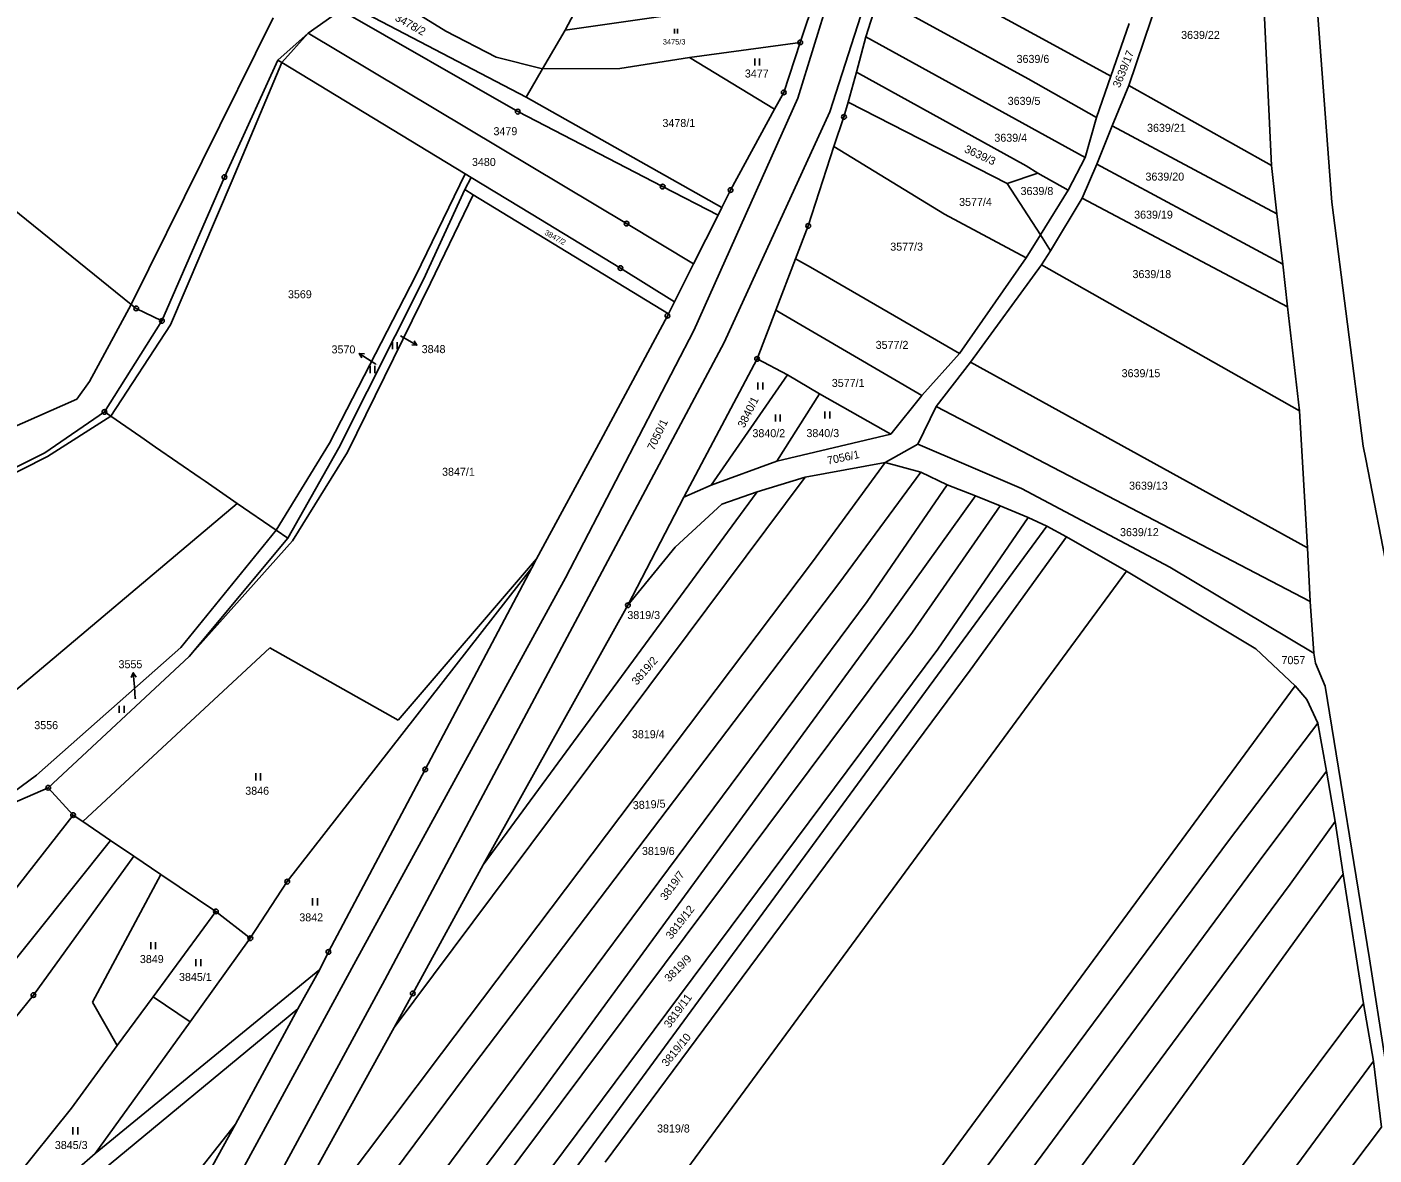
# Model space of a CAD drawing. Extents: x -593183 to -588034, y -1130415 to -1124994.
# Drawn here: x -592616.5 to -592330.3, y -1129503.7 to -1129264.2 of the extents above; entities that cross this region are included whole.
import ezdxf

# ---------------------------------------------------------------- set-up
doc = ezdxf.new("R2010")
doc.units = 0
for name, color, linetype in [('Vrstva 1', 7, 'Continuous'), ('Vrstva 16', 7, 'Continuous'), ('Vrstva 18', 7, 'Continuous'), ('Vrstva 24', 7, 'Continuous'), ('Vrstva 25', 7, 'Continuous'), ('Vrstva 4', 7, 'Continuous')]:
    doc.layers.add(name, color=color, linetype=linetype)

msp = doc.modelspace()

# ---------------------------------------------------------------- linework, layer by layer
at = {"layer": 'Vrstva 1'}
for p, q in [((-592502.17, -1129264.93), (-592488.76, -1129239.64)), ((-592372.43, -1129247.28), (-592382.39, -1129276.63)), ((-592433.18, -1129249.11), (-592399.16, -1129267.58)), ((-592547.28, -1129252.87), (-592527.55, -1129265.11)), ((-592448.45, -1129256.14), (-592452.23, -1129267.51)), ((-592435.59, -1129257.8), (-592438.25, -1129266.31)), ((-592435.59, -1129257.8), (-592403.79, -1129275.27)), ((-592353.74, -1129259.3), (-592352.1, -1129293.67)), ((-592342.42, -1129259), (-592339.24, -1129301.4)), ((-592564.21, -1129262.32), (-592594.34, -1129323.16)), ((-592549.85, -1129260.67), (-592556.77, -1129265.52)), ((-592549.85, -1129260.67), (-592512.23, -1129282.21)), ((-592502.17, -1129264.93), (-592475.9, -1129261.13)), ((-592527.55, -1129265.11), (-592516.81, -1129270.62)), ((-592506.96, -1129273.15), (-592502.17, -1129264.93)), ((-592386.24, -1129274.66), (-592382.35, -1129263.47)), ((-592556.77, -1129265.52), (-592563.19, -1129271.28)), ((-592556.77, -1129265.52), (-592489.11, -1129305.98)), ((-592475.78, -1129270.69), (-592452.23, -1129267.51)), ((-592455.72, -1129278.13), (-592452.23, -1129267.51)), ((-592438.25, -1129266.31), (-592440.26, -1129273.86)), ((-592438.25, -1129266.31), (-592391.7, -1129291.93)), ((-592399.16, -1129267.58), (-592386.24, -1129274.66)), ((-592516.81, -1129270.62), (-592506.96, -1129273.15)), ((-592490.56, -1129273.03), (-592475.78, -1129270.69)), ((-592475.78, -1129270.69), (-592457.69, -1129281.69)), ((-592563.19, -1129271.28), (-592574.56, -1129296.11)), ((-592563.19, -1129271.28), (-592562.34, -1129271.8)), ((-592562.34, -1129271.8), (-592523.43, -1129295.39)), ((-592506.96, -1129273.15), (-592510.46, -1129279.15)), ((-592506.96, -1129273.15), (-592490.56, -1129273.03)), ((-592440.26, -1129273.86), (-592442.04, -1129280.18)), ((-592440.26, -1129273.86), (-592404.18, -1129293.74)), ((-592403.79, -1129275.27), (-592389.3, -1129283.48)), ((-592389.3, -1129283.48), (-592386.24, -1129274.66)), ((-592382.39, -1129276.63), (-592385.96, -1129285.21)), ((-592382.39, -1129276.63), (-592352.1, -1129293.67)), ((-592510.46, -1129279.15), (-592468.85, -1129302.54)), ((-592457.69, -1129281.69), (-592455.72, -1129278.13)), ((-592512.23, -1129282.21), (-592481.45, -1129298.11)), ((-592457.69, -1129281.69), (-592467.01, -1129298.87)), ((-592442.04, -1129280.18), (-592442.92, -1129283.33)), ((-592442.04, -1129280.18), (-592408.23, -1129297.46)), ((-592442.92, -1129283.33), (-592445.06, -1129289.63)), ((-592391.7, -1129291.93), (-592389.3, -1129283.48)), ((-592385.96, -1129285.21), (-592389.19, -1129293.36)), ((-592385.96, -1129285.21), (-592350.93, -1129303.88)), ((-592450.52, -1129306.46), (-592445.06, -1129289.63)), ((-592445.06, -1129289.63), (-592421.59, -1129303.96)), ((-592404.18, -1129293.74), (-592401.75, -1129295.29)), ((-592395.3, -1129298.88), (-592391.7, -1129291.93)), ((-592389.19, -1129293.36), (-592392.33, -1129300.61)), ((-592389.19, -1129293.36), (-592349.69, -1129314.61)), ((-592352.1, -1129293.67), (-592350.93, -1129303.88)), ((-592629.53, -1129294.78), (-592594.34, -1129323.16)), ((-592574.56, -1129296.11), (-592587.83, -1129326.65)), ((-592533.9, -1129317.03), (-592523.43, -1129295.39)), ((-592522.15, -1129296.17), (-592523.48, -1129298.75)), ((-592523.43, -1129295.39), (-592522.15, -1129296.17)), ((-592522.15, -1129296.17), (-592509.4, -1129303.91)), ((-592401.75, -1129295.29), (-592408.23, -1129297.46)), ((-592401.75, -1129295.29), (-592395.3, -1129298.88)), ((-592523.48, -1129298.75), (-592532.29, -1129317.84)), ((-592523.48, -1129298.75), (-592521.71, -1129299.9)), ((-592481.45, -1129298.11), (-592469.69, -1129304.19)), ((-592467.01, -1129298.87), (-592468.85, -1129302.54)), ((-592408.23, -1129297.46), (-592401.17, -1129308.35)), ((-592395.3, -1129298.88), (-592401.17, -1129308.35)), ((-592521.71, -1129299.9), (-592530.77, -1129318.6)), ((-592521.71, -1129299.9), (-592480.21, -1129325.16)), ((-592468.85, -1129302.54), (-592469.69, -1129304.19)), ((-592392.33, -1129300.61), (-592399.01, -1129311.78)), ((-592392.33, -1129300.61), (-592348.66, -1129323.62)), ((-592339.24, -1129301.4), (-592332.6, -1129353.21)), ((-592509.4, -1129303.91), (-592490.42, -1129315.43)), ((-592474.88, -1129314.49), (-592469.69, -1129304.19)), ((-592421.59, -1129303.96), (-592404.19, -1129313.23)), ((-592350.93, -1129303.88), (-592349.69, -1129314.61)), ((-592489.11, -1129305.98), (-592474.88, -1129314.49)), ((-592453.21, -1129313.45), (-592450.52, -1129306.46)), ((-592401.17, -1129308.35), (-592404.19, -1129313.23)), ((-592401.17, -1129308.35), (-592399.01, -1129311.78)), ((-592457.4, -1129324.37), (-592453.21, -1129313.45)), ((-592453.21, -1129313.45), (-592450.07, -1129315.26)), ((-592404.19, -1129313.23), (-592418.36, -1129333.55)), ((-592399.01, -1129311.78), (-592400.95, -1129314.72)), ((-592490.42, -1129315.43), (-592478.93, -1129322.6)), ((-592478.93, -1129322.6), (-592474.88, -1129314.49)), ((-592450.07, -1129315.26), (-592418.36, -1129333.55)), ((-592416.06, -1129335.42), (-592400.95, -1129314.72)), ((-592400.95, -1129314.72), (-592346.12, -1129345.7)), ((-592349.69, -1129314.61), (-592348.66, -1129323.62)), ((-592552.25, -1129352.59), (-592533.9, -1129317.03)), ((-592550.28, -1129353.58), (-592532.29, -1129317.84)), ((-592530.77, -1129318.6), (-592548.4, -1129354.52)), ((-592480.21, -1129325.16), (-592478.93, -1129322.6)), ((-592603.26, -1129339.52), (-592594.34, -1129323.16)), ((-592594.34, -1129323.16), (-592593.3, -1129324)), ((-592593.3, -1129324), (-592587.83, -1129326.65)), ((-592480.21, -1129325.16), (-592480.45, -1129325.55)), ((-592461.37, -1129334.71), (-592457.4, -1129324.37)), ((-592457.4, -1129324.37), (-592456.67, -1129324.8)), ((-592456.67, -1129324.8), (-592426.38, -1129342.5)), ((-592348.66, -1129323.62), (-592346.12, -1129345.7)), ((-592587.83, -1129326.65), (-592600.05, -1129345.96)), ((-592480.45, -1129325.55), (-592494.59, -1129351.94)), ((-592418.36, -1129333.55), (-592426.38, -1129342.5)), ((-592476.93, -1129364.09), (-592461.37, -1129334.71)), ((-592461.37, -1129334.71), (-592454.95, -1129338.11)), ((-592423.37, -1129344.79), (-592416.06, -1129335.42)), ((-592416.06, -1129335.42), (-592344.41, -1129374.8)), ((-592605.95, -1129343.28), (-592603.26, -1129339.52)), ((-592471.12, -1129361.54), (-592454.95, -1129338.11)), ((-592454.95, -1129338.11), (-592448.13, -1129342.09)), ((-592457.18, -1129356.39), (-592448.13, -1129342.09)), ((-592448.13, -1129342.09), (-592432.98, -1129350.71)), ((-592426.38, -1129342.5), (-592432.98, -1129350.71)), ((-592638.13, -1129357.46), (-592605.95, -1129343.28)), ((-592427.26, -1129352.84), (-592423.37, -1129344.79)), ((-592423.37, -1129344.79), (-592343.89, -1129386.22)), ((-592600.05, -1129345.96), (-592612.74, -1129354.62)), ((-592598.73, -1129346.87), (-592612.18, -1129355.44)), ((-592600.05, -1129345.96), (-592598.73, -1129346.87)), ((-592598.73, -1129346.87), (-592592.31, -1129351.28)), ((-592346.12, -1129345.7), (-592344.41, -1129374.8)), ((-592432.98, -1129350.71), (-592457.18, -1129356.39)), ((-592592.31, -1129351.28), (-592589.18, -1129353.43)), ((-592589.18, -1129353.43), (-592579.72, -1129359.95)), ((-592552.25, -1129352.59), (-592563.58, -1129371.04)), ((-592561.07, -1129372.77), (-592550.28, -1129353.58)), ((-592494.59, -1129351.94), (-592508.27, -1129377.17)), ((-592434.18, -1129356.68), (-592427.26, -1129352.84)), ((-592427.26, -1129352.84), (-592405.17, -1129362.25)), ((-592332.6, -1129353.21), (-592332.07, -1129355.97)), ((-592612.74, -1129354.62), (-592625.77, -1129361.15)), ((-592612.18, -1129355.44), (-592625.16, -1129361.95)), ((-592548.4, -1129354.52), (-592560.11, -1129373.31)), ((-592457.18, -1129356.39), (-592471.12, -1129361.54)), ((-592451.18, -1129359.81), (-592434.18, -1129356.68)), ((-592449.63, -1129377.77), (-592434.18, -1129356.68)), ((-592434.18, -1129356.68), (-592426.58, -1129358.74)), ((-592332.07, -1129355.97), (-592327.01, -1129381.91)), ((-592451.18, -1129359.81), (-592538.53, -1129476.7)), ((-592461.37, -1129362.95), (-592451.18, -1129359.81)), ((-592426.58, -1129358.74), (-592444, -1129382.37)), ((-592426.58, -1129358.74), (-592420.99, -1129361.46)), ((-592579.72, -1129359.95), (-592578.65, -1129360.68)), ((-592578.65, -1129360.68), (-592571.82, -1129365.38)), ((-592471.12, -1129361.54), (-592476.93, -1129364.09)), ((-592420.99, -1129361.46), (-592438.02, -1129386.19)), ((-592420.99, -1129361.46), (-592415.01, -1129363.8)), ((-592405.17, -1129362.25), (-592373.69, -1129378.91)), ((-592571.82, -1129365.38), (-592625.68, -1129410.77)), ((-592571.82, -1129365.38), (-592563.58, -1129371.04)), ((-592476.93, -1129364.09), (-592488.83, -1129387)), ((-592468.86, -1129365.56), (-592461.37, -1129362.95)), ((-592461.37, -1129362.95), (-592465.88, -1129369.1)), ((-592415.01, -1129363.8), (-592433.12, -1129389.07)), ((-592415.01, -1129363.8), (-592409.77, -1129365.91)), ((-592478.77, -1129374.68), (-592468.86, -1129365.56)), ((-592409.77, -1129365.91), (-592428.37, -1129392.7)), ((-592403.81, -1129368.39), (-592422.95, -1129396.37)), ((-592409.77, -1129365.91), (-592403.81, -1129368.39)), ((-592403.81, -1129368.39), (-592399.79, -1129370.25)), ((-592563.58, -1129371.04), (-592583.8, -1129395.99)), ((-592563.58, -1129371.04), (-592561.07, -1129372.77)), ((-592465.88, -1129369.1), (-592519.59, -1129442.1)), ((-592399.79, -1129370.25), (-592497.07, -1129502.63)), ((-592399.79, -1129370.25), (-592395.63, -1129372.45)), ((-592582.03, -1129397.89), (-592561.07, -1129372.77)), ((-592560.11, -1129373.31), (-592582.03, -1129397.89)), ((-592395.63, -1129372.45), (-592416.09, -1129400.77)), ((-592395.63, -1129372.45), (-592382.89, -1129379.81)), ((-592488.83, -1129387), (-592478.77, -1129374.68)), ((-592344.41, -1129374.8), (-592343.89, -1129386.22)), ((-592509.21, -1129379.05), (-592561.2, -1129445.7)), ((-592537.66, -1129411.4), (-592508.27, -1129377.17)), ((-592509.21, -1129379.05), (-592531.89, -1129421.87)), ((-592528.41, -1129482.16), (-592449.63, -1129377.77)), ((-592508.27, -1129377.17), (-592509.21, -1129379.05)), ((-592382.89, -1129379.81), (-592404.58, -1129409.23)), ((-592382.89, -1129379.81), (-592355.42, -1129396.25)), ((-592373.69, -1129378.91), (-592343.09, -1129397.21)), ((-592444, -1129382.37), (-592523.23, -1129486.72)), ((-592438.02, -1129386.19), (-592571.09, -1129565.21)), ((-592488.83, -1129387), (-592519.59, -1129442.1)), ((-592343.89, -1129386.22), (-592343.09, -1129397.21)), ((-592433.12, -1129389.07), (-592508.72, -1129492.45)), ((-592428.37, -1129392.7), (-592615.11, -1129642.53)), ((-592583.8, -1129395.99), (-592614.52, -1129423.06)), ((-592604.64, -1129432.96), (-592564.92, -1129396.07)), ((-592537.66, -1129411.4), (-592564.92, -1129396.07)), ((-592422.95, -1129396.37), (-592556.78, -1129575.72)), ((-592355.42, -1129396.25), (-592347.06, -1129404.11)), ((-592612, -1129425.77), (-592582.03, -1129397.89)), ((-592343.09, -1129397.21), (-592342.77, -1129399.3)), ((-592342.77, -1129399.3), (-592340.69, -1129404.16)), ((-592416.09, -1129400.77), (-592493.66, -1129505.27)), ((-592347.06, -1129404.11), (-592422.06, -1129506.07)), ((-592347.06, -1129404.11), (-592344.55, -1129407.03)), ((-592340.69, -1129404.16), (-592331.28, -1129462.11)), ((-592344.55, -1129407.03), (-592342.25, -1129412.06)), ((-592404.58, -1129409.23), (-592534.96, -1129586.45)), ((-592342.25, -1129412.06), (-592361, -1129436.75)), ((-592342.25, -1129412.06), (-592340.38, -1129422.25)), ((-592552.45, -1129460.63), (-592531.89, -1129421.87)), ((-592340.38, -1129422.25), (-592354.68, -1129441.35)), ((-592340.38, -1129422.25), (-592338.57, -1129432.91)), ((-592614.52, -1129423.06), (-592626.89, -1129432.2)), ((-592626.89, -1129432.2), (-592612, -1129425.77)), ((-592612, -1129425.77), (-592606.7, -1129431.58)), ((-592606.7, -1129431.58), (-592635.24, -1129467.95)), ((-592606.7, -1129431.58), (-592604.64, -1129432.96)), ((-592604.64, -1129432.96), (-592598.77, -1129436.95)), ((-592338.57, -1129432.91), (-592348.11, -1129446.26)), ((-592338.57, -1129432.91), (-592336.85, -1129444.12)), ((-592598.77, -1129436.95), (-592728.12, -1129598.57)), ((-592598.77, -1129436.95), (-592593.78, -1129440.28)), ((-592361, -1129436.75), (-592443.04, -1129547.16)), ((-592593.78, -1129440.28), (-592615.14, -1129469.78)), ((-592593.78, -1129440.28), (-592588.04, -1129444.15)), ((-592519.59, -1129442.1), (-592534.54, -1129469.44)), ((-592354.68, -1129441.35), (-592435.72, -1129550.87)), ((-592588.04, -1129444.15), (-592602.57, -1129471.27)), ((-592588.04, -1129444.15), (-592576.37, -1129452.02)), ((-592542.16, -1129727.88), (-592336.85, -1129444.12)), ((-592336.85, -1129444.12), (-592332.56, -1129471.56)), ((-592569.06, -1129457.7), (-592561.2, -1129445.7)), ((-592348.11, -1129446.26), (-592429.15, -1129555.51)), ((-592589.69, -1129470.13), (-592576.37, -1129452.02)), ((-592576.37, -1129452.02), (-592569.06, -1129457.7)), ((-592581.87, -1129475.49), (-592569.06, -1129457.7)), ((-592554.32, -1129464.36), (-592552.45, -1129460.63)), ((-592331.28, -1129462.11), (-592324.59, -1129504.82)), ((-592601.99, -1129503.41), (-592554.32, -1129464.36)), ((-592554.32, -1129464.36), (-592558.93, -1129472.7)), ((-592615.14, -1129469.78), (-592673.78, -1129542.41)), ((-592602.57, -1129471.27), (-592597.32, -1129480.5)), ((-592597.32, -1129480.5), (-592589.69, -1129470.13)), ((-592589.69, -1129470.13), (-592581.87, -1129475.49)), ((-592534.54, -1129469.44), (-592538.53, -1129476.7)), ((-592558.93, -1129472.7), (-592609.92, -1129514.75)), ((-592558.93, -1129472.7), (-592572.22, -1129497.21)), ((-592332.56, -1129471.56), (-592403.4, -1129566.28)), ((-592332.56, -1129471.56), (-592330.41, -1129483.83)), ((-592581.87, -1129475.49), (-592601.99, -1129503.41)), ((-592538.53, -1129476.7), (-592561.73, -1129518.61)), ((-592597.32, -1129480.5), (-592607.08, -1129493.77)), ((-592528.41, -1129482.16), (-592577.74, -1129547.59)), ((-592330.41, -1129483.83), (-592400.03, -1129577.94)), ((-592330.41, -1129483.83), (-592328.74, -1129497.8)), ((-592523.23, -1129486.72), (-592578.35, -1129560.66)), ((-592619.46, -1129509.25), (-592607.08, -1129493.77)), ((-592508.72, -1129492.45), (-592566.4, -1129568.69)), ((-592572.22, -1129497.21), (-592660.77, -1129609.53)), ((-592572.22, -1129497.21), (-592578.59, -1129508.75)), ((-592328.74, -1129497.8), (-592392.56, -1129582.82)), ((-592553.2, -1129578.42), (-592497.07, -1129502.63)), ((-592614.6, -1129514.29), (-592601.99, -1129503.41))]:
    msp.add_line(p, q, dxfattribs=at)
at = {"layer": 'Vrstva 16'}
for p, q in [((-592537.16, -1129329.81), (-592536.27, -1129330.31)), ((-592542.36, -1129335.83), (-592543.4, -1129335.16)), ((-592593.52, -1129406.91), (-592593.7, -1129404.34))]:
    msp.add_line(p, q, dxfattribs=at)
at = {"layer": 'Vrstva 24'}
for centre, radius in [((-592452.23, -1129267.51), 0.5), ((-592452.23, -1129267.51), 0.0327), ((-592455.72, -1129278.13), 0.5), ((-592455.72, -1129278.13), 0.0327), ((-592512.23, -1129282.21), 0.5), ((-592512.23, -1129282.21), 0.0327), ((-592442.92, -1129283.33), 0.5), ((-592442.92, -1129283.33), 0.0327), ((-592574.56, -1129296.11), 0.5), ((-592574.56, -1129296.11), 0.0327), ((-592481.45, -1129298.11), 0.5), ((-592481.45, -1129298.11), 0.0327), ((-592467.01, -1129298.87), 0.5), ((-592467.01, -1129298.87), 0.0327), ((-592489.11, -1129305.98), 0.5), ((-592489.11, -1129305.98), 0.0327), ((-592450.52, -1129306.46), 0.5), ((-592450.52, -1129306.46), 0.0327), ((-592490.42, -1129315.43), 0.5), ((-592490.42, -1129315.43), 0.0327), ((-592593.3, -1129324), 0.5), ((-592593.3, -1129324), 0.0327), ((-592480.45, -1129325.55), 0.5), ((-592587.83, -1129326.65), 0.5), ((-592587.83, -1129326.65), 0.0327), ((-592480.45, -1129325.55), 0.0327), ((-592461.37, -1129334.71), 0.5), ((-592461.37, -1129334.71), 0.0327), ((-592600.05, -1129345.96), 0.5), ((-592600.05, -1129345.96), 0.0327), ((-592488.83, -1129387), 0.5), ((-592488.83, -1129387), 0.0327), ((-592531.89, -1129421.87), 0.5), ((-592531.89, -1129421.87), 0.0327), ((-592612, -1129425.77), 0.5), ((-592612, -1129425.77), 0.0327), ((-592606.7, -1129431.58), 0.5), ((-592606.7, -1129431.58), 0.0327), ((-592561.2, -1129445.7), 0.5), ((-592561.2, -1129445.7), 0.0327), ((-592576.37, -1129452.02), 0.5), ((-592576.37, -1129452.02), 0.0327), ((-592569.06, -1129457.7), 0.5), ((-592569.06, -1129457.7), 0.0327), ((-592552.45, -1129460.63), 0.5), ((-592552.45, -1129460.63), 0.0327), ((-592615.14, -1129469.78), 0.5), ((-592615.14, -1129469.78), 0.0327), ((-592534.54, -1129469.44), 0.5), ((-592534.54, -1129469.44), 0.0327)]:
    msp.add_circle(centre, radius, dxfattribs=at)
at = {"layer": 'Vrstva 25'}
for p, q in [((-592478.95, -1129264.64), (-592478.95, -1129265.64)), ((-592478.26, -1129265.64), (-592478.26, -1129264.64)), ((-592461.89, -1129270.94), (-592461.89, -1129272.44)), ((-592460.86, -1129272.44), (-592460.86, -1129270.94)), ((-592538.85, -1129331.14), (-592538.85, -1129332.64)), ((-592537.83, -1129332.64), (-592537.83, -1129331.14)), ((-592536.27, -1129330.31), (-592533.65, -1129331.78)), ((-592543.4, -1129335.16), (-592545.92, -1129333.54)), ((-592543.61, -1129336.2), (-592543.61, -1129337.7)), ((-592542.59, -1129337.7), (-592542.59, -1129336.2)), ((-592461.2, -1129339.7), (-592461.2, -1129341.2)), ((-592460.18, -1129341.2), (-592460.18, -1129339.7)), ((-592457.49, -1129346.49), (-592457.49, -1129347.99)), ((-592456.47, -1129347.99), (-592456.47, -1129346.49)), ((-592446.97, -1129345.89), (-592446.97, -1129347.39)), ((-592445.95, -1129347.39), (-592445.95, -1129345.89)), ((-592593.7, -1129404.34), (-592593.92, -1129401.35)), ((-592596.9, -1129408.36), (-592596.9, -1129409.86)), ((-592595.88, -1129409.86), (-592595.88, -1129408.36)), ((-592567.9, -1129422.69), (-592567.9, -1129424.19)), ((-592566.88, -1129424.19), (-592566.88, -1129422.69)), ((-592555.84, -1129449.24), (-592555.84, -1129450.74)), ((-592554.82, -1129450.74), (-592554.82, -1129449.24)), ((-592590.22, -1129458.52), (-592590.22, -1129460.02)), ((-592589.2, -1129460.02), (-592589.2, -1129458.52)), ((-592580.62, -1129462.15), (-592580.62, -1129463.65)), ((-592579.59, -1129463.65), (-592579.59, -1129462.15)), ((-592606.74, -1129497.85), (-592606.74, -1129499.35)), ((-592605.72, -1129499.35), (-592605.72, -1129497.85))]:
    msp.add_line(p, q, dxfattribs=at)
for points in [[(-592534.28, -1129330.85), (-592533.65, -1129331.78), (-592534.77, -1129331.72)], [(-592545.35, -1129334.5), (-592545.92, -1129333.54), (-592544.81, -1129333.66)], [(-592594.34, -1129402.38), (-592593.92, -1129401.35), (-592593.34, -1129402.31)]]:
    msp.add_lwpolyline(points, dxfattribs=at)
at = {"layer": 'Vrstva 4'}
for p, q in [((-592442.49, -1129246.13), (-592452.73, -1129279.36)), ((-592435.06, -1129248.51), (-592445.9, -1129282.28)), ((-592549.25, -1129258.86), (-592510.46, -1129279.15)), ((-592556.77, -1129265.52), (-592562.34, -1129271.8)), ((-592562.34, -1129271.8), (-592572.91, -1129296.83)), ((-592452.73, -1129279.36), (-592474.79, -1129328.7)), ((-592445.9, -1129282.28), (-592468.38, -1129331.19)), ((-592572.91, -1129296.83), (-592586, -1129327.45)), ((-592586, -1129327.45), (-592598.73, -1129346.87)), ((-592468.38, -1129331.19), (-592519.58, -1129427.25)), ((-592474.79, -1129328.7), (-592502.07, -1129381.18)), ((-592547.08, -1129463.27), (-592502.07, -1129381.18)), ((-592540.45, -1129466.53), (-592519.58, -1129427.25)), ((-592573.41, -1129511.78), (-592547.08, -1129463.27)), ((-592567.02, -1129515.52), (-592540.45, -1129466.53))]:
    msp.add_line(p, q, dxfattribs=at)

# ---------------------------------------------------------------- texts
at = {"layer": 'Vrstva 16'}
for s, p in [('3570', (-592551.8, -1129333.54)), ('3848', (-592532.65, -1129333.48)), ('3555', (-592597.06, -1129400.38))]:
    msp.add_text(s, height=1.7, dxfattribs=at).set_placement(p)
at = {"layer": 'Vrstva 18'}
for s, height, rotation, p in [('3478/2', 1.7, 330.6558, (-592538.47, -1129262.74)), ('3639/17', 1.7, 67.9217, (-592384.33, -1129277.27)), ('3639/3', 1.7, 335.2249, (-592417.5, -1129290.74)), ('3847/2', 1.14, 330.72, (-592506.65, -1129308.24)), ('3840/1', 1.7, 63.2307, (-592464.11, -1129349.5)), ('7050/1', 1.7, 64.3665, (-592483.29, -1129354.27)), ('7056/1', 1.7, 11.9239, (-592446.31, -1129357.16)), ('3819/2', 1.7, 49.1489, (-592486.92, -1129404.1)), ('3819/5', 1.7, 3.1363, (-592487.74, -1129430.34)), ('3819/7', 1.7, 53.9726, (-592480.77, -1129449.84)), ('3819/12', 1.7, 52.1951, (-592479.61, -1129458.07)), ('3819/9', 1.7, 45, (-592480.06, -1129467.14)), ('3819/11', 1.7, 53.7122, (-592479.98, -1129476.92)), ('3819/10', 1.7, 50.5437, (-592480.52, -1129485.12))]:
    msp.add_text(s, height=height, rotation=rotation, dxfattribs=at).set_placement(p)
for s, height, p in [('3639/22', 1.7, (-592371.29, -1129266.77)), ('3475/3', 1.14, (-592481.41, -1129267.95)), ('3639/6', 1.7, (-592406.25, -1129271.86)), ('3477', 1.7, (-592463.98, -1129274.96)), ('3639/5', 1.7, (-592408.14, -1129280.77)), ('3478/1', 1.7, (-592481.49, -1129285.47)), ('3639/21', 1.7, (-592378.53, -1129286.49)), ('3479', 1.7, (-592517.39, -1129287.21)), ('3639/4', 1.7, (-592410.97, -1129288.6)), ('3480', 1.7, (-592521.97, -1129293.74)), ('3639/20', 1.7, (-592378.86, -1129296.85)), ('3639/8', 1.7, (-592405.4, -1129299.91)), ('3577/4', 1.7, (-592418.46, -1129302.23)), ('3639/19', 1.7, (-592381.27, -1129304.93)), ('3577/3', 1.7, (-592433.09, -1129311.72)), ('3639/18', 1.7, (-592381.62, -1129317.55)), ('3569', 1.7, (-592561.06, -1129321.83)), ('3848', 0.1, (-592537.16, -1129329.81)), ('3577/2', 1.7, (-592436.19, -1129332.58)), ('3570', 0.1, (-592542.36, -1129335.83)), ('3639/15', 1.7, (-592383.93, -1129338.59)), ('3577/1', 1.7, (-592445.51, -1129340.66)), ('3840/2', 1.7, (-592462.37, -1129351.33)), ('3840/3', 1.7, (-592450.9, -1129351.31)), ('3847/1', 1.7, (-592528.32, -1129359.52)), ('3639/13', 1.7, (-592382.35, -1129362.47)), ('3639/12', 1.7, (-592384.27, -1129372.34)), ('3819/3', 1.7, (-592488.95, -1129389.94)), ('7057', 1.7, (-592349.96, -1129399.52)), ('3555', 0.1, (-592593.52, -1129406.91)), ('3556', 1.7, (-592614.96, -1129413.32)), ('3819/4', 1.7, (-592487.98, -1129415.24)), ('3846', 1.7, (-592570.13, -1129427.25)), ('3819/6', 1.7, (-592485.85, -1129440.03)), ('3842', 1.7, (-592558.65, -1129454.13)), ('3849', 1.7, (-592592.52, -1129462.99)), ('3845/1', 1.7, (-592584.21, -1129466.79)), ('3819/8', 1.7, (-592482.64, -1129498.96)), ('3845/3', 1.7, (-592610.59, -1129502.47))]:
    msp.add_text(s, height=height, dxfattribs=at).set_placement(p)

doc.saveas('drawing.dxf')
